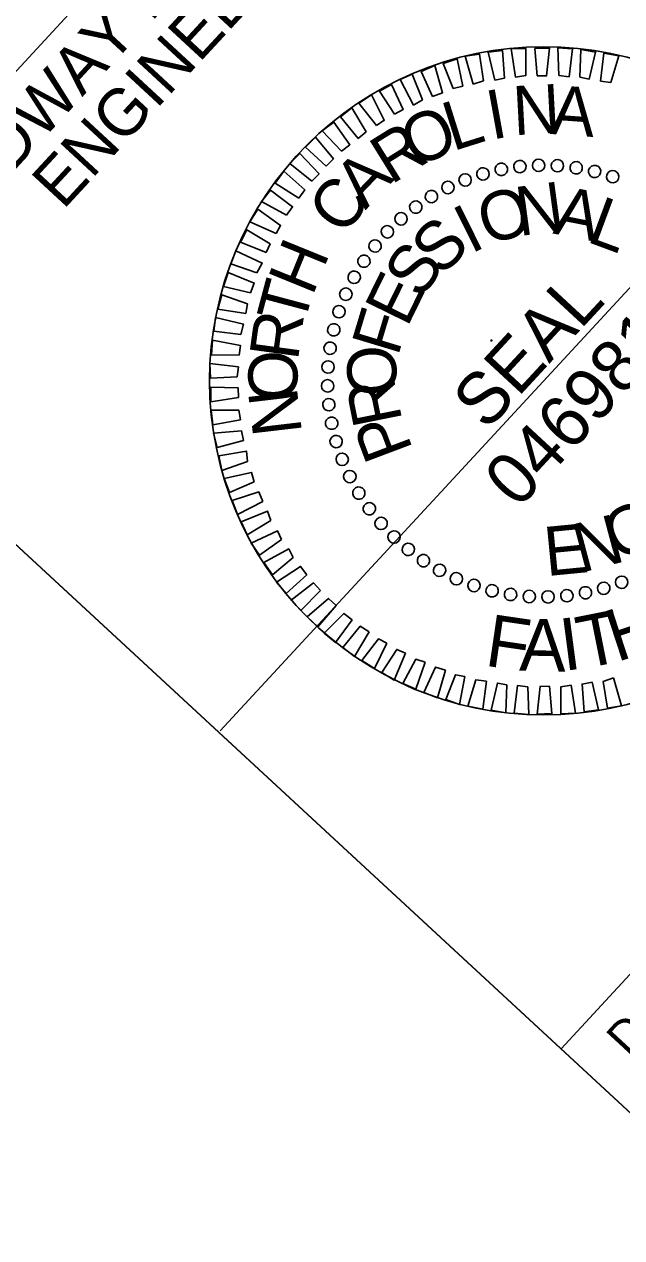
# Model space of a CAD drawing. Extents: x 1768274 to 1769121, y 999922 to 1000687.
# Drawn here: x 1768969.17 to 1768981.8, y 1000266.93 to 1000292.6 of the extents above; entities that cross this region are included whole.
import ezdxf

# ---------------------------------------------------------------- set-up
doc = ezdxf.new("R2010")
doc.units = 0
for name, color, linetype in [('E_NCDOT_Terrain_Model_Contour_Imported', 7, 'Continuous'), ('E_NCDOT_Terrain_Model_Contour_Major', 7, 'Continuous'), ('E_NCDOT_Terrain_Model_Void', 7, 'Continuous')]:
    doc.layers.add(name, color=color, linetype=linetype)

msp = doc.modelspace()

# ---------------------------------------------------------------- linework, layer by layer
at = {"layer": 'E_NCDOT_Terrain_Model_Contour_Imported'}
msp.add_line((1768986.989, 1000292.453), (1768973.311, 1000277.656), dxfattribs=at)
msp.add_lwpolyline([(1768737.288, 1000073.608), (1768947.711, 1000301.251), (1769102.655, 1000158.029), (1768892.232, 999930.385)], close=True, dxfattribs=at)
msp.add_circle((1768980.15, 1000285.055), 7.065, dxfattribs=at)
at = {"layer": 'E_NCDOT_Terrain_Model_Contour_Major'}
for p, q in [((1769102.655, 1000158.029), (1768947.714, 1000301.255)), ((1768977.573, 1000300.89), (1768963.998, 1000286.203))]:
    msp.add_line(p, q, dxfattribs=at)
msp.add_lwpolyline([(1768980.521, 1000270.929), (1768994.098, 1000285.617), (1768995.969, 1000283.888), (1768982.392, 1000269.2)], close=True, dxfattribs=at)
msp.add_circle((1768979.047, 1000285.91), 0.012, dxfattribs=at)
at = {"layer": 'E_NCDOT_Terrain_Model_Void'}
for p, q in [((1768979.255, 1000289.53), (1768979.255, 1000289.53)), ((1768979.652, 1000289.597), (1768979.652, 1000289.597)), ((1768980.044, 1000289.619), (1768980.044, 1000289.619)), ((1768980.449, 1000289.615), (1768980.449, 1000289.615)), ((1768980.838, 1000289.566), (1768980.838, 1000289.566)), ((1768981.234, 1000289.485), (1768981.234, 1000289.485)), ((1768978.491, 1000289.306), (1768978.491, 1000289.306)), ((1768978.865, 1000289.443), (1768978.865, 1000289.443)), ((1768981.618, 1000289.378), (1768981.618, 1000289.378)), ((1768978.123, 1000289.15), (1768978.123, 1000289.15)), ((1768977.451, 1000288.731), (1768977.451, 1000288.731)), ((1768977.77, 1000288.956), (1768977.77, 1000288.956)), ((1768977.138, 1000288.487), (1768977.138, 1000288.487)), ((1768976.847, 1000288.211), (1768976.847, 1000288.211)), ((1768976.581, 1000287.911), (1768976.581, 1000287.911)), ((1768976.356, 1000287.587), (1768976.356, 1000287.587)), ((1768976.138, 1000287.243), (1768976.138, 1000287.243)), ((1768975.958, 1000286.888), (1768975.958, 1000286.888)), ((1768975.818, 1000286.522), (1768975.818, 1000286.522)), ((1768975.711, 1000286.138), (1768975.711, 1000286.138)), ((1768975.63, 1000285.742), (1768975.63, 1000285.742)), ((1768975.581, 1000285.353), (1768975.581, 1000285.353)), ((1768975.577, 1000284.948), (1768975.577, 1000284.948)), ((1768980.146, 1000285.05), (1768980.146, 1000285.05)), ((1768975.599, 1000284.556), (1768975.599, 1000284.556)), ((1768975.666, 1000284.159), (1768975.666, 1000284.159)), ((1768975.752, 1000283.769), (1768975.752, 1000283.769)), ((1768975.89, 1000283.395), (1768975.89, 1000283.395)), ((1768976.046, 1000283.027), (1768976.046, 1000283.027)), ((1768976.24, 1000282.674), (1768976.24, 1000282.674)), ((1768976.465, 1000282.355), (1768976.465, 1000282.355)), ((1768976.709, 1000282.042), (1768976.709, 1000282.042)), ((1768976.985, 1000281.751), (1768976.985, 1000281.751)), ((1768977.285, 1000281.485), (1768977.285, 1000281.485)), ((1768977.609, 1000281.26), (1768977.609, 1000281.26)), ((1768977.953, 1000281.042), (1768977.953, 1000281.042)), ((1768978.308, 1000280.862), (1768978.308, 1000280.862)), ((1768981.801, 1000280.794), (1768981.801, 1000280.794)), ((1768978.674, 1000280.722), (1768978.674, 1000280.722)), ((1768979.058, 1000280.615), (1768979.058, 1000280.615)), ((1768979.454, 1000280.534), (1768979.454, 1000280.534)), ((1768980.64, 1000280.503), (1768980.64, 1000280.503)), ((1768981.037, 1000280.57), (1768981.037, 1000280.57)), ((1768981.426, 1000280.656), (1768981.426, 1000280.656)), ((1768979.842, 1000280.485), (1768979.842, 1000280.485)), ((1768980.248, 1000280.481), (1768980.248, 1000280.481))]:
    msp.add_line(p, q, dxfattribs=at)
for points in [[(1768979.116, 1000291.418), (1768978.977, 1000292.005), (1768979.285, 1000292.042), (1768979.327, 1000291.458)], [(1768979.558, 1000291.48), (1768979.464, 1000292.075), (1768979.773, 1000292.087), (1768979.776, 1000291.514)], [(1768980.015, 1000291.504), (1768979.966, 1000292.082), (1768980.275, 1000292.094), (1768980.214, 1000291.506)], [(1768980.471, 1000291.516), (1768980.455, 1000292.101), (1768980.765, 1000292.075), (1768980.691, 1000291.486)], [(1768980.917, 1000291.476), (1768980.939, 1000292.062), (1768981.251, 1000292.01), (1768981.118, 1000291.438)], [(1768978.241, 1000291.235), (1768978.027, 1000291.768), (1768978.326, 1000291.863), (1768978.439, 1000291.288)], [(1768978.663, 1000291.329), (1768978.491, 1000291.921), (1768978.792, 1000291.965), (1768978.879, 1000291.402)], [(1768981.352, 1000291.396), (1768981.425, 1000291.985), (1768981.743, 1000291.927), (1768981.572, 1000291.366)], [(1768977.398, 1000290.886), (1768977.119, 1000291.429), (1768977.373, 1000291.542), (1768977.587, 1000290.997)], [(1768977.803, 1000291.07), (1768977.563, 1000291.601), (1768977.848, 1000291.722), (1768978.013, 1000291.149)], [(1768977, 1000290.697), (1768976.678, 1000291.18), (1768976.937, 1000291.325), (1768977.177, 1000290.794)], [(1768976.617, 1000290.456), (1768976.244, 1000290.925), (1768976.507, 1000291.103), (1768976.78, 1000290.566)], [(1768976.228, 1000290.183), (1768975.856, 1000290.639), (1768976.093, 1000290.829), (1768976.396, 1000290.325)], [(1768975.878, 1000289.912), (1768975.468, 1000290.34), (1768975.712, 1000290.524), (1768976.053, 1000290.048)], [(1768975.549, 1000289.596), (1768975.115, 1000289.998), (1768975.325, 1000290.212), (1768975.704, 1000289.751)], [(1768975.246, 1000289.282), (1768974.781, 1000289.65), (1768974.991, 1000289.864), (1768975.401, 1000289.436)], [(1768974.97, 1000288.917), (1768974.475, 1000289.239), (1768974.658, 1000289.491), (1768975.099, 1000289.096)], [(1768974.714, 1000288.559), (1768974.187, 1000288.847), (1768974.371, 1000289.086), (1768974.842, 1000288.738)], [(1768974.491, 1000288.17), (1768973.94, 1000288.419), (1768974.103, 1000288.689), (1768974.587, 1000288.341)], [(1768974.281, 1000287.769), (1768973.738, 1000287.986), (1768973.87, 1000288.249), (1768974.364, 1000287.953)], [(1768974.086, 1000287.343), (1768973.537, 1000287.527), (1768973.642, 1000287.802), (1768974.2, 1000287.547)], [(1768973.954, 1000286.919), (1768973.382, 1000287.051), (1768973.48, 1000287.345), (1768974.03, 1000287.122)], [(1768973.849, 1000286.483), (1768973.259, 1000286.57), (1768973.344, 1000286.876), (1768973.886, 1000286.684)], [(1768973.744, 1000286.035), (1768973.175, 1000286.103), (1768973.208, 1000286.394), (1768973.8, 1000286.256)], [(1768973.71, 1000285.596), (1768973.123, 1000285.605), (1768973.15, 1000285.915), (1768973.74, 1000285.803)], [(1768973.67, 1000285.137), (1768973.104, 1000285.114), (1768973.092, 1000285.423), (1768973.694, 1000285.35)], [(1768973.7, 1000284.7), (1768973.111, 1000284.612), (1768973.112, 1000284.922), (1768973.692, 1000284.906)], [(1768973.738, 1000284.231), (1768973.156, 1000284.125), (1768973.118, 1000284.432), (1768973.704, 1000284.436)], [(1768973.806, 1000283.796), (1768973.246, 1000283.645), (1768973.169, 1000283.951), (1768973.76, 1000284)], [(1768973.888, 1000283.348), (1768973.342, 1000283.159), (1768973.278, 1000283.466), (1768973.867, 1000283.567)], [(1768974.027, 1000282.922), (1768973.508, 1000282.696), (1768973.394, 1000282.988), (1768973.975, 1000283.12)], [(1768974.211, 1000282.505), (1768973.675, 1000282.232), (1768973.56, 1000282.524), (1768974.126, 1000282.707)], [(1768974.382, 1000282.099), (1768973.879, 1000281.796), (1768973.752, 1000282.074), (1768974.309, 1000282.302)], [(1768974.61, 1000281.702), (1768974.14, 1000281.368), (1768973.963, 1000281.619), (1768974.519, 1000281.885)], [(1768974.85, 1000281.319), (1768974.414, 1000280.954), (1768974.23, 1000281.211), (1768974.76, 1000281.502)], [(1768975.142, 1000280.95), (1768974.706, 1000280.56), (1768974.504, 1000280.796), (1768975.012, 1000281.132)], [(1768975.432, 1000280.62), (1768975.017, 1000280.198), (1768974.809, 1000280.416), (1768975.284, 1000280.782)], [(1768975.76, 1000280.305), (1768975.378, 1000279.852), (1768975.151, 1000280.062), (1768975.599, 1000280.453)], [(1768976.1, 1000280.003), (1768975.752, 1000279.519), (1768975.512, 1000279.716), (1768975.927, 1000280.138)], [(1768976.458, 1000279.746), (1768976.15, 1000279.225), (1768975.904, 1000279.415), (1768976.273, 1000279.868)], [(1768976.834, 1000279.51), (1768976.572, 1000278.971), (1768976.308, 1000279.141), (1768976.657, 1000279.599)], [(1768977.229, 1000279.294), (1768976.988, 1000278.724), (1768976.73, 1000278.887), (1768977.046, 1000279.376)], [(1768977.649, 1000279.104), (1768977.446, 1000278.536), (1768977.171, 1000278.654), (1768977.447, 1000279.167)], [(1768978.074, 1000278.934), (1768977.91, 1000278.354), (1768977.616, 1000278.465), (1768977.865, 1000279.003)], [(1768978.485, 1000278.802), (1768978.373, 1000278.211), (1768978.086, 1000278.316), (1768978.284, 1000278.839)], [(1768978.94, 1000278.704), (1768978.866, 1000278.115), (1768978.549, 1000278.173), (1768978.72, 1000278.734)], [(1768981.629, 1000278.771), (1768981.801, 1000278.179), (1768981.5, 1000278.135), (1768981.413, 1000278.698)], [(1768979.374, 1000278.624), (1768979.352, 1000278.037), (1768979.041, 1000278.09), (1768979.173, 1000278.662)], [(1768979.82, 1000278.584), (1768979.837, 1000277.998), (1768979.527, 1000278.025), (1768979.6, 1000278.614)], [(1768980.277, 1000278.595), (1768980.326, 1000278.018), (1768980.017, 1000278.006), (1768980.078, 1000278.594)], [(1768980.734, 1000278.62), (1768980.828, 1000278.025), (1768980.519, 1000278.012), (1768980.516, 1000278.585)], [(1768981.176, 1000278.682), (1768981.315, 1000278.095), (1768981.007, 1000278.057), (1768980.965, 1000278.642)]]:
    msp.add_lwpolyline(points, close=True, dxfattribs=at)
for centre, major_axis in [((1768980.046, 1000289.614), (-0.003, 0.131)), ((1768980.444, 1000289.605), (0.009, 0.131)), ((1768978.868, 1000289.433), (-0.037, 0.126)), ((1768979.255, 1000289.527), (-0.026, 0.129)), ((1768979.649, 1000289.588), (-0.014, 0.13)), ((1768980.84, 1000289.562), (0.02, 0.13)), ((1768981.231, 1000289.484), (0.031, 0.127)), ((1768981.613, 1000289.373), (0.042, 0.124)), ((1768978.127, 1000289.144), (-0.058, 0.118)), ((1768978.491, 1000289.305), (-0.048, 0.122)), ((1768977.778, 1000288.953), (-0.068, 0.112)), ((1768977.446, 1000288.731), (-0.077, 0.106)), ((1768977.136, 1000288.482), (-0.0864, 0.0985)), ((1768976.848, 1000288.207), (-0.0947, 0.0906)), ((1768976.586, 1000287.907), (-0.102, 0.082)), ((1768976.35, 1000287.586), (-0.109, 0.073)), ((1768976.144, 1000287.246), (-0.115, 0.063)), ((1768975.967, 1000286.888), (-0.12, 0.053)), ((1768975.823, 1000286.517), (-0.124, 0.042)), ((1768975.712, 1000286.135), (-0.127, 0.031)), ((1768975.634, 1000285.744), (-0.13, 0.02)), ((1768975.591, 1000285.348), (-0.131, 0.009)), ((1768975.582, 1000284.95), (-0.131, -0.003)), ((1768975.608, 1000284.553), (-0.13, -0.014)), ((1768975.669, 1000284.159), (-0.129, -0.026)), ((1768975.763, 1000283.772), (-0.126, -0.037)), ((1768975.891, 1000283.395), (-0.122, -0.048)), ((1768976.052, 1000283.031), (-0.118, -0.058)), ((1768976.243, 1000282.682), (-0.112, -0.068)), ((1768976.465, 1000282.35), (-0.106, -0.077)), ((1768976.714, 1000282.04), (-0.0985, -0.0864)), ((1768976.989, 1000281.752), (-0.0906, -0.0947)), ((1768977.289, 1000281.49), (-0.082, -0.102)), ((1768977.61, 1000281.254), (-0.073, -0.109)), ((1768977.95, 1000281.048), (-0.063, -0.115)), ((1768978.307, 1000280.871), (-0.053, -0.12)), ((1768978.679, 1000280.727), (-0.042, -0.124)), ((1768979.061, 1000280.616), (-0.031, -0.127)), ((1768981.423, 1000280.667), (0.037, -0.126)), ((1768981.801, 1000280.795), (0.048, -0.122)), ((1768979.452, 1000280.538), (-0.02, -0.13)), ((1768979.847, 1000280.495), (-0.009, -0.131)), ((1768980.246, 1000280.486), (0.003, -0.131)), ((1768980.643, 1000280.512), (0.014, -0.13)), ((1768981.037, 1000280.573), (0.026, -0.129))]:
    msp.add_ellipse(centre, major_axis=major_axis, ratio=0.999708, dxfattribs=at)

# ---------------------------------------------------------------- texts
at = {"layer": 'E_NCDOT_Terrain_Model_Contour_Major'}
for s, height, p in [('ROADWAY DESIGN ', 1.00003, (1768966.91, 1000287.288)), ('ENGINEER', 1, (1768969.987, 1000288.657)), ('DOCUMENT NOT CONSIDERED FINAL', 0.72007, (1768981.954, 1000270.734))]:
    msp.add_text(s, height=height, rotation=47.2512, dxfattribs=at).set_placement(p)
at = {"layer": 'E_NCDOT_Terrain_Model_Void'}
for s, height, rotation, p in [('N', 1.038, 3.0701, (1768979.523, 1000290.249)), ('A', 1.037, 355.8684, (1768980.282, 1000290.278)), ('I', 1.037, 10.2714, (1768979.05, 1000290.153)), ('O', 1.032, 24.6724, (1768977.438, 1000289.548)), ('L', 1.035, 17.4721, (1768978.229, 1000289.908)), ('R', 1.03, 31.8723, (1768976.924, 1000289.193)), ('A', 1.026, 46.2715, (1768976.378, 1000288.657)), ('C', 1.027, 53.4711, (1768975.93, 1000288.091)), ('N', 1.038, 7.7278, (1768979.633, 1000288.115)), ('O', 1.035, 17.0847, (1768978.951, 1000287.914)), ('A', 1.035, 349.0115, (1768980.332, 1000288.174)), ('I', 1.032, 26.4408, (1768978.611, 1000287.733)), ('L', 1.032, 339.6521, (1768981.034, 1000288.009)), ('S', 1.026, 45.1516, (1768977.986, 1000287.245)), ('H', 1.032, 67.8707, (1768975.259, 1000286.829)), ('S', 1.027, 54.5068, (1768977.548, 1000286.758)), ('T', 1.035, 75.071, (1768975.078, 1000286.19)), ('E', 1.03, 63.8623, (1768977.262, 1000286.167)), ('SEAL', 1.0918, 47.2512, (1768978.945, 1000283.979)), ('R', 1.037, 82.2717, (1768974.952, 1000285.464)), ('F', 1.034, 73.2183, (1768977.067, 1000285.554)), ('046981', 1.0918, 47.2512, (1768979.614, 1000282.327)), ('O', 1.038, 89.473, (1768974.94, 1000284.62)), ('O', 1.038, 91.9325, (1768977.054, 1000284.748)), ('R', 1.036, 101.2909, (1768977.165, 1000284.211)), ('N', 1.037, 96.6747, (1768975.043, 1000283.954)), ('P', 1.033, 110.6501, (1768977.395, 1000283.602)), ('G', 1.033, 24.2415, (1768981.713, 1000281.222)), ('E', 1.038, 5.5281, (1768980.211, 1000280.924)), ('N', 1.036, 14.8852, (1768980.943, 1000280.992)), ('H', 1.101, 18.1246, (1768981.697, 1000279.103)), ('F', 1.102, 351.6655, (1768978.885, 1000279.035)), ('A', 1.104, 358.6821, (1768979.629, 1000278.926)), ('I', 1.104, 7.5224, (1768980.577, 1000278.919)), ('T', 1.103, 11.3243, (1768980.982, 1000278.961))]:
    msp.add_text(s, height=height, rotation=rotation, dxfattribs=at).set_placement(p)

doc.saveas('drawing.dxf')
